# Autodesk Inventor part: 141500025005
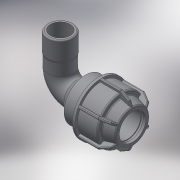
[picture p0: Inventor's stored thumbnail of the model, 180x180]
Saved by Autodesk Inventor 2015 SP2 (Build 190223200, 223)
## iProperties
Created: 2017-08
Part Number: 141500025005
Material: Generic
Description: L.14 90° ELBOW FEMALE ADAPTOR (SILVER) 25-1/2"
Document SubType Name: Modeling
Designer: KIM
Density: 1 g/cm^3
Appearance: Default
Author: KIM
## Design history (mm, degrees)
derived "141500.ipt"
feature "Solid1::141500.ipt"
feature "Solid2::141500.ipt"
tag "TaggingFeature1"
body "Solid1"
body "Solid2"
other parameters: "d1" = 25, "d2" = 48, "d4" = 15 deg, "d5" = 31.68, "d6" = 10.4544, "d16" = 25.5, "d17" = 2.4, "d24" = 2.4, "d25" = 45, "d26" = 37.5, "d27" = 2.4, "d28" = 135 deg, "d29" = 1.44, "d31" = 1.25, "d46" = 150 deg, "d49" = 2.5, "d50" = 0, "d58" = 0.75, "d61" = 360 deg, "d63" = 22.5, "d94" = 45, "d95" = 18.631, "d96" = 24.2203, "d97" = 18, "d98" = 14.9048, "d99" = 23.49369, "d100" = 135 deg, "d108" = 1.25, "d112" = 23.4, "d113" = 68, "d114" = 52.8, "d115" = 23.49369, "d116" = 45 deg, "d117" = 0, "d118" = 0, "d_" = 25, "G_" = 18.631, "A_" = 68, "l_" = 48, "l_2" = 18, "A_1" = 45
